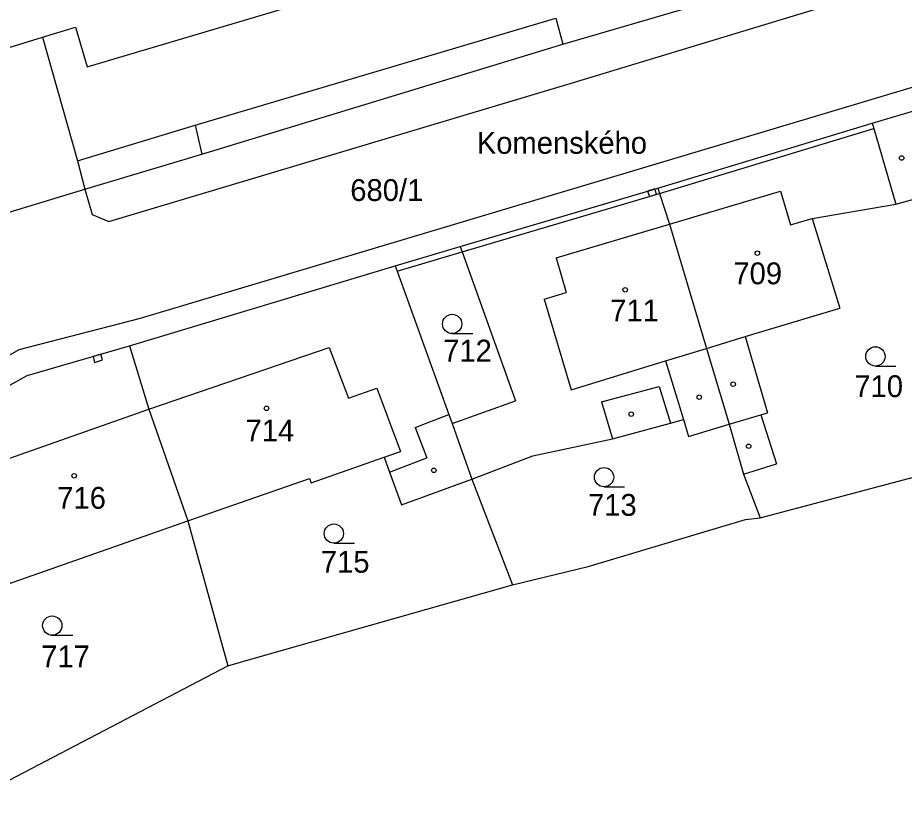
# Model space of a CAD drawing. Extents: x -785744 to -782822, y -1067550 to -1063910.
# Drawn here: x -783351.7 to -783282.6, y -1065736.5 to -1065675.9 of the extents above; entities that cross this region are included whole.
import ezdxf

# ---------------------------------------------------------------- set-up
doc = ezdxf.new("R2010")
doc.units = 0
for name, color, linetype in [('Hranice kat_území', 7, 'Continuous'), ('Hranice parcel', 7, 'Continuous'), ('Parcelní čísla', 7, 'Continuous'), ('Pop_ČP_popisy', 7, 'Continuous'), ('Vnitřní kresba', 7, 'Continuous'), ('Věcná břemena k části', 7, 'Continuous'), ('Značky budov', 7, 'Continuous'), ('Značky kultur', 7, 'Continuous')]:
    doc.layers.add(name, color=color, linetype=linetype)

msp = doc.modelspace()

# ---------------------------------------------------------------- linework, layer by layer
at = {"layer": 'Hranice kat_území'}
msp.add_lwpolyline([(-783354.62, -1065736.48), (-783335.33, -1065726.39), (-783333.18, -1065725.78), (-783313.14, -1065720.08), (-783307.25, -1065718.67), (-783294.97, -1065715), (-783293.84, -1065714.87), (-783274.13, -1065709.64)], dxfattribs=at)
at = {"layer": 'Hranice parcel'}
for points in [[(-783346.29, -1065679.74), (-783304.76, -1065667.39)], [(-783309.2, -1065677.97), (-783298.7, -1065674.89)], [(-783349.78, -1065677.43), (-783347.21, -1065676.64)], [(-783347.21, -1065676.64), (-783346.29, -1065679.74)], [(-783355.52, -1065679.18), (-783349.78, -1065677.43)], [(-783337.36, -1065686.53), (-783309.2, -1065677.97)], [(-783285.09, -1065684.11), (-783281.6, -1065683.09)], [(-783301.81, -1065689.17), (-783285.09, -1065684.11)], [(-783346.46, -1065689.26), (-783337.36, -1065686.53)], [(-783352.36, -1065691.04), (-783346.46, -1065689.26)], [(-783317.21, -1065693.73), (-783301.81, -1065689.17)], [(-783301.81, -1065689.17), (-783301.67, -1065689.59)], [(-783301.67, -1065689.59), (-783300.9, -1065691.99)], [(-783283.25, -1065690.42), (-783279.79, -1065689.46)], [(-783289.77, -1065691.55), (-783283.25, -1065690.42)], [(-783289.77, -1065691.55), (-783287.62, -1065698.54)], [(-783300.9, -1065691.99), (-783298.01, -1065701.67)], [(-783322.29, -1065695.24), (-783317.21, -1065693.73)], [(-783317.21, -1065693.73), (-783317.06, -1065694.15)], [(-783317.06, -1065694.15), (-783312.89, -1065705.74)], [(-783343, -1065701.47), (-783322.29, -1065695.24)], [(-783322.29, -1065695.24), (-783322.13, -1065695.66)], [(-783322.13, -1065695.66), (-783318.1, -1065706.82)], [(-783294.99, -1065700.75), (-783287.62, -1065698.54)], [(-783294.99, -1065700.75), (-783293.27, -1065706.69)], [(-783350.96, -1065703.79), (-783343, -1065701.47)], [(-783343, -1065701.47), (-783341.49, -1065706.4)], [(-783298.01, -1065701.67), (-783296.26, -1065707.58)], [(-783365.46, -1065711.85), (-783350.96, -1065703.79)], [(-783317.85, -1065707.51), (-783312.89, -1065705.74)], [(-783341.49, -1065706.4), (-783338.43, -1065715.11)], [(-783318.1, -1065706.82), (-783317.85, -1065707.51)], [(-783293.78, -1065706.84), (-783293.27, -1065706.69)], [(-783293.78, -1065706.84), (-783292.57, -1065710.66)], [(-783317.85, -1065707.51), (-783316.31, -1065711.85)], [(-783305.35, -1065708.71), (-783300.83, -1065707.49)], [(-783300.83, -1065707.49), (-783299.81, -1065707.21)], [(-783299.81, -1065707.21), (-783299.42, -1065708.52)], [(-783299.42, -1065708.52), (-783296.26, -1065707.58)], [(-783296.26, -1065707.58), (-783295.13, -1065711.46)], [(-783311.56, -1065710.03), (-783305.35, -1065708.71)], [(-783328.83, -1065712.15), (-783323.14, -1065710.15)], [(-783323.14, -1065710.15), (-783322.72, -1065711.31)], [(-783316.31, -1065711.85), (-783311.56, -1065710.03)], [(-783295.13, -1065711.46), (-783292.57, -1065710.66)], [(-783338.43, -1065715.11), (-783328.95, -1065711.79)], [(-783328.95, -1065711.79), (-783328.83, -1065712.15)], [(-783322.72, -1065711.31), (-783321.79, -1065713.86)], [(-783321.79, -1065713.86), (-783316.31, -1065711.85)], [(-783316.31, -1065711.85), (-783313.14, -1065720.08)], [(-783295.13, -1065711.46), (-783293.84, -1065714.87)], [(-783352.5, -1065720.04), (-783338.43, -1065715.11)], [(-783338.43, -1065715.11), (-783335.33, -1065726.39)]]:
    msp.add_lwpolyline(points, dxfattribs=at)
at = {"layer": 'Vnitřní kresba'}
for points in [[(-783342.12, -1065699.3), (-783217.82, -1065662.09)], [(-783308.37, -1065680.94), (-783246.23, -1065662.1)], [(-783337.87, -1065684.28), (-783309.77, -1065675.94)], [(-783309.77, -1065675.94), (-783309.2, -1065677.97)], [(-783349.78, -1065677.43), (-783347.05, -1065687.05)], [(-783344.6, -1065691.79), (-783308.37, -1065680.94)], [(-783347.05, -1065687.05), (-783337.87, -1065684.28)], [(-783337.87, -1065684.28), (-783337.36, -1065686.53)], [(-783285.09, -1065684.11), (-783284.96, -1065684.53)], [(-783301.67, -1065689.59), (-783284.96, -1065684.53)], [(-783284.96, -1065684.53), (-783283.25, -1065690.42)], [(-783347.05, -1065687.05), (-783346.46, -1065689.26)], [(-783346.46, -1065689.26), (-783345.91, -1065691.23)], [(-783317.06, -1065694.15), (-783301.67, -1065689.59)], [(-783300.9, -1065691.99), (-783292.24, -1065689.42)], [(-783292.24, -1065689.42), (-783291.46, -1065692.03)], [(-783345.91, -1065691.23), (-783344.6, -1065691.79)], [(-783291.46, -1065692.03), (-783289.77, -1065691.55)], [(-783309.74, -1065694.62), (-783300.9, -1065691.99)], [(-783322.13, -1065695.66), (-783317.06, -1065694.15)], [(-783309.74, -1065694.62), (-783308.94, -1065697.3)], [(-783310.66, -1065697.82), (-783308.94, -1065697.3)], [(-783310.66, -1065697.82), (-783308.56, -1065704.89)], [(-783351.6, -1065701.75), (-783342.12, -1065699.3)], [(-783298.01, -1065701.67), (-783294.99, -1065700.75)], [(-783341.49, -1065706.4), (-783327.42, -1065701.6)], [(-783327.42, -1065701.6), (-783325.91, -1065705.54)], [(-783366.51, -1065710.32), (-783351.6, -1065701.75)], [(-783301.2, -1065702.64), (-783298.01, -1065701.67)], [(-783308.56, -1065704.89), (-783301.2, -1065702.64)], [(-783301.2, -1065702.64), (-783299.81, -1065707.21)], [(-783325.91, -1065705.54), (-783323.72, -1065704.77)], [(-783323.72, -1065704.77), (-783321.86, -1065709.71)], [(-783306.19, -1065705.83), (-783301.7, -1065704.64)], [(-783301.7, -1065704.64), (-783300.83, -1065707.49)], [(-783355.59, -1065711.36), (-783341.49, -1065706.4)], [(-783306.19, -1065705.83), (-783305.35, -1065708.71)], [(-783320.71, -1065707.82), (-783318.1, -1065706.82)], [(-783296.26, -1065707.58), (-783293.78, -1065706.84)], [(-783320.71, -1065707.82), (-783319.81, -1065710.2)], [(-783323.14, -1065710.15), (-783321.86, -1065709.71)], [(-783322.72, -1065711.31), (-783319.81, -1065710.2)]]:
    msp.add_lwpolyline(points, dxfattribs=at)
at = {"layer": 'Věcná břemena k části'}
for points in [[(-783302.05, -1065689.24), (-783302.61, -1065689.41)], [(-783302.61, -1065689.41), (-783302.47, -1065689.83)], [(-783302.47, -1065689.83), (-783301.92, -1065689.66)], [(-783301.92, -1065689.66), (-783302.05, -1065689.24)], [(-783345.21, -1065702.12), (-783345.82, -1065702.29)], [(-783345.82, -1065702.29), (-783345.71, -1065702.76)], [(-783345.08, -1065702.55), (-783345.21, -1065702.12)], [(-783345.71, -1065702.76), (-783345.08, -1065702.55)]]:
    msp.add_lwpolyline(points, dxfattribs=at)
at = {"layer": 'Značky budov'}
for centre in [(-783282.8, -1065686.83), (-783294.05, -1065694.25), (-783304.35, -1065697.1), (-783295.94, -1065704.45), (-783298.58, -1065705.46), (-783332.31, -1065706.33), (-783303.88, -1065706.79), (-783294.73, -1065709.29), (-783319.27, -1065711.17), (-783347.3, -1065711.59)]:
    msp.add_circle(centre, 0.175, dxfattribs=at)
at = {"layer": 'Značky kultur'}
for p, q in [((-783317.84, -1065700.51), (-783316.24, -1065700.51)), ((-783284.85, -1065703.04), (-783283.25, -1065703.04)), ((-783306, -1065712.45), (-783304.4, -1065712.45)), ((-783327.06, -1065716.84), (-783325.46, -1065716.84)), ((-783349.01, -1065724.01), (-783347.41, -1065724.01))]:
    msp.add_line(p, q, dxfattribs=at)
for centre in [(-783317.84, -1065699.76), (-783284.85, -1065702.29), (-783306, -1065711.7), (-783327.06, -1065716.09), (-783349.01, -1065723.26)]:
    msp.add_circle(centre, 0.75, dxfattribs=at)

# ---------------------------------------------------------------- texts
at = {"layer": 'Parcelní čísla'}
for s, p in [('680/1', (-783325.78, -1065690.18)), ('709', (-783295.92, -1065696.67)), ('711', (-783305.52, -1065699.56)), ('712', (-783318.54, -1065702.69)), ('710', (-783286.49, -1065705.46)), ('714', (-783333.94, -1065708.91)), ('716', (-783348.62, -1065714.16)), ('713', (-783307.25, -1065714.71)), ('715', (-783328.07, -1065719.14)), ('717', (-783349.87, -1065726.51))]:
    msp.add_text(s, height=1.7, dxfattribs=at).set_placement(p)
at = {"layer": 'Pop_ČP_popisy'}
msp.add_text('Komenského', height=1.7, dxfattribs=at).set_placement((-783315.92, -1065686.5))

doc.saveas('drawing.dxf')
